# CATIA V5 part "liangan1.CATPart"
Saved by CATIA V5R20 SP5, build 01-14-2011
Part number: 连杆1
Bounding box of the stored display mesh (mm): x -20 to 170, y -20 to 20, z 0 to 40
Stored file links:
  E:\scc\liangan\liangan.CATPart
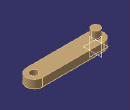
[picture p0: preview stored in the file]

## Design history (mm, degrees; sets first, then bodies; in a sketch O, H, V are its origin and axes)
Body1 (main body)
  Sketch1 on xy-plane, origin (0, 0, 0), H (1, 0, 0), V (0, 1, 0)
    construction line L1 (0, 0) -> (150, 0)
    line L2 (0, 20) -> (150, 20)
    line L3 (150, -20) -> (0, -20)
    arc A1 centre (150, 0) radius 20 from (150, 20) to (150, -20) cw
    arc A2 centre (0, 0) radius 20 from (0, -20) to (0, 20) cw
    circle A3 centre (150, 0) radius 10
    distance L1 L2 = 20
    radius A3 = 10
    horizontal: L1 H
    tangency: A1 L2, A2 L2, A1 L3, A2 L3
  Pad1: profile Sketch1, direction (0, 0, 1), length 20
  Sketch2 on end face of Pad1, origin (0, 0, 20), H (1, 0, 0), V (0, 1, 0)
    circle A1 centre (0, 0) radius 10
    radius A1 = 10
  Pad2: profile Sketch2, direction (0, 0, 1), length 20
